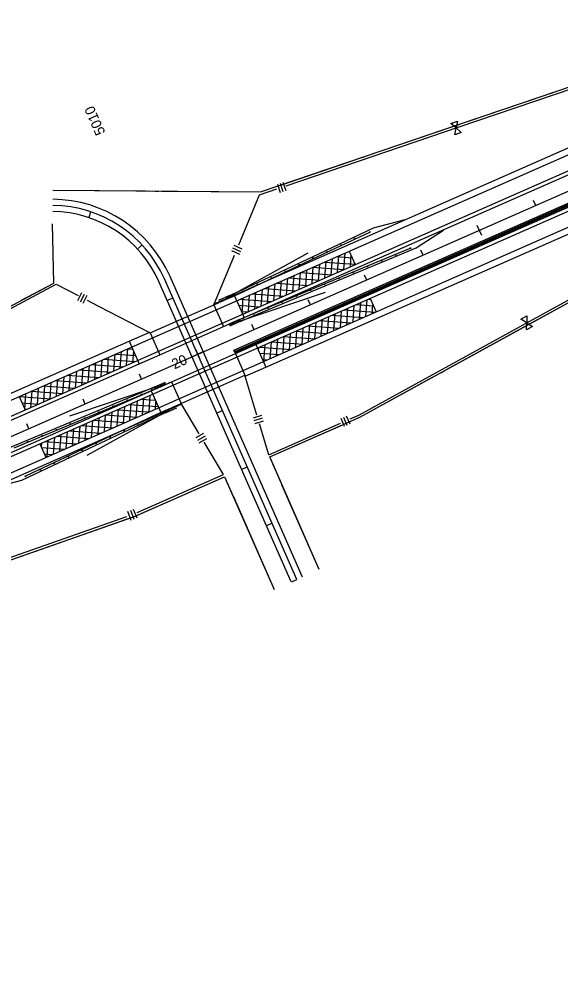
# Model space of a CAD drawing. Extents: x 192699 to 285914, y 194342 to 233219.
# Drawn here: x 245592 to 246471, y 222360 to 223895 of the extents above; entities that cross this region are included whole.
import ezdxf

# ---------------------------------------------------------------- set-up
doc = ezdxf.new("R2010")
doc.units = 0
for name, color, linetype in [('CENT LINE', 7, 'Continuous'), ('CONCRETE', 7, 'Continuous'), ('GUARDRAIL', 7, 'Continuous'), ('PAVEMENT TRANSITION', 7, 'Continuous'), ('R-W - CofA', 7, 'Continuous'), ('R_Draft', 7, 'Continuous'), ('R_Proposed Guardrail', 7, 'Continuous'), ('ROAD', 7, 'Continuous'), ('SHOULDER', 7, 'Continuous'), ('STATIONING1', 7, 'Continuous'), ('STATIONING2', 7, 'Continuous'), ('WRSF', 7, 'Continuous')]:
    doc.layers.add(name, color=color, linetype=linetype)

msp = doc.modelspace()

# ---------------------------------------------------------------- linework, layer by layer
at = {"layer": 'CENT LINE'}
for p, q in [((229622.3, 216190.7), (246993.1, 223840)), ((245646.8, 223592.4), (245646.7, 223592.4)), ((246043.2, 222984.7), (245828.2, 223473))]:
    msp.add_line(p, q, dxfattribs=at)
msp.add_arc((245645.1, 223392.4), 200, 23.7666, 89.5335, dxfattribs=at)
at = {"layer": 'CONCRETE'}
for p, q in [((245941.1, 223357.1), (247000.3, 223823.5)), ((245942.7, 223353.4), (247001.9, 223819.9)), ((245942.7, 223353.4), (245941.1, 223357.1))]:
    msp.add_line(p, q, dxfattribs=at)
at = {"layer": 'GUARDRAIL'}
for p, q in [((245929.5, 223442.3), (246061.8, 223515.5)), ((245946.7, 223403.1), (246090, 223451.3)), ((245817.3, 223298.4), (245674, 223250.2)), ((245834.6, 223259.2), (245702.3, 223186.1))]:
    msp.add_line(p, q, dxfattribs=at)
at = {"layer": 'PAVEMENT TRANSITION'}
for p, q in [((246109.6, 223483.7), (246111.5, 223510.8)), ((246119.9, 223488.3), (246121.9, 223515.4)), ((246127.3, 223517.8), (246128.8, 223517.7)), ((246128.5, 223518.3), (246138.2, 223496.3)), ((246130.3, 223492.9), (246131.6, 223511.2)), ((246078.5, 223470.1), (246080.5, 223497.2)), ((246088.1, 223500.5), (246137.9, 223497)), ((246088.9, 223474.6), (246090.8, 223501.7)), ((246099.2, 223479.2), (246101.2, 223506.3)), ((246107.7, 223509.2), (246133.3, 223507.3)), ((246047.4, 223456.4), (246049.4, 223483.5)), ((246049, 223483.3), (246100.2, 223479.6)), ((246057.8, 223461), (246059.7, 223488)), ((246068.1, 223465.5), (246070.1, 223492.6)), ((246068.6, 223491.9), (246119.7, 223488.2)), ((246006, 223438.2), (246008, 223465.2)), ((246009.9, 223466.1), (246061, 223462.4)), ((246016.4, 223442.7), (246018.3, 223469.8)), ((246026.7, 223447.3), (246028.7, 223474.4)), ((246029.4, 223474.7), (246080.6, 223471)), ((246037.1, 223451.8), (246039, 223478.9)), ((245975, 223424.5), (245976.9, 223451.6)), ((245985.3, 223429), (245987.3, 223456.1)), ((245990.3, 223457.4), (246041.5, 223453.8)), ((245995.7, 223433.6), (245997.6, 223460.7)), ((245945.8, 223436.9), (245945.9, 223437.9)), ((245951.2, 223440.2), (246002.3, 223436.5)), ((245954.4, 223417.4), (245956.2, 223442.4)), ((245964.6, 223419.9), (245966.6, 223447)), ((245970.7, 223448.8), (246021.9, 223445.1)), ((246145.2, 223407.6), (246147.1, 223434.7)), ((246155.5, 223412.2), (246157.5, 223439.3)), ((246158.8, 223439.9), (246163.2, 223439.6)), ((246162.3, 223441.4), (246172, 223419.5)), ((245948.7, 223430.4), (245982.8, 223427.9)), ((245953.2, 223420), (245963.2, 223419.3)), ((246114.1, 223394), (246116, 223421)), ((246119.7, 223422.6), (246170.8, 223419)), ((246124.4, 223398.5), (246126.4, 223425.6)), ((246134.8, 223403.1), (246136.7, 223430.2)), ((246139.2, 223431.3), (246167.7, 223429.2)), ((246165.9, 223416.8), (246166.9, 223431.1)), ((246080.5, 223405.4), (246131.7, 223401.7)), ((246083, 223380.3), (246085, 223407.4)), ((246093.4, 223384.8), (246095.3, 223411.9)), ((246100.1, 223414), (246151.3, 223410.3)), ((246103.7, 223389.4), (246105.7, 223416.5)), ((246041.4, 223388.2), (246092.6, 223384.5)), ((246041.6, 223362), (246043.6, 223389.1)), ((246052, 223366.6), (246053.9, 223393.7)), ((246061, 223396.8), (246112.1, 223393.1)), ((246062.3, 223371.2), (246064.3, 223398.2)), ((246072.7, 223375.7), (246074.6, 223402.8)), ((246010.5, 223348.4), (246012.5, 223375.4)), ((246020.9, 223352.9), (246022.9, 223380)), ((246021.8, 223379.5), (246073, 223375.9)), ((246031.3, 223357.5), (246033.2, 223384.6)), ((245766.6, 223332.7), (245768.6, 223359.8)), ((245768.2, 223359.6), (245776.7, 223359)), ((245981.1, 223356.8), (245981.4, 223361.8)), ((245982.7, 223362.3), (246033.9, 223358.6)), ((245989.8, 223339.2), (245991.8, 223366.3)), ((246000.2, 223343.8), (246002.1, 223370.9)), ((246002.2, 223370.9), (246053.4, 223367.2)), ((245729, 223342.4), (245780.2, 223338.7)), ((245735.6, 223319.1), (245737.5, 223346.1)), ((245745.9, 223323.6), (245747.9, 223350.7)), ((245748.6, 223351), (245781.2, 223348.7)), ((245756.3, 223328.2), (245758.2, 223355.3)), ((245777, 223337.3), (245778.3, 223355.4)), ((245983.1, 223352.3), (246014.3, 223350)), ((245987.6, 223341.9), (245994.7, 223341.4)), ((245694.1, 223300.8), (245696.1, 223327.9)), ((245704.5, 223305.4), (245706.5, 223332.5)), ((245709.5, 223333.8), (245760.6, 223330.1)), ((245714.9, 223309.9), (245716.8, 223337)), ((245725.2, 223314.5), (245727.2, 223341.6)), ((245663.1, 223287.1), (245665, 223314.2)), ((245670.3, 223316.5), (245721.5, 223312.9)), ((245673.4, 223291.7), (245675.4, 223318.8)), ((245683.8, 223296.3), (245685.7, 223323.3)), ((245689.9, 223325.2), (245741.1, 223321.5)), ((245621.7, 223268.9), (245623.6, 223296)), ((245631.2, 223299.3), (245682.4, 223295.6)), ((245632, 223273.5), (245634, 223300.5)), ((245642.4, 223278), (245644.3, 223305.1)), ((245650.8, 223307.9), (245701.9, 223304.2)), ((245652.7, 223282.6), (245654.7, 223309.7)), ((245592, 223282.1), (245601.7, 223260.1)), ((245592, 223282.1), (245643.2, 223278.4)), ((245592.5, 223281.1), (245592.6, 223282.3)), ((245601.1, 223261.5), (245602.9, 223286.9)), ((245611.3, 223264.3), (245613.3, 223291.4)), ((245611.6, 223290.7), (245662.8, 223287)), ((245803.1, 223257), (245805.1, 223284.1)), ((245596.6, 223271.7), (245623.7, 223269.8)), ((245761.7, 223238.8), (245763.7, 223265.9)), ((245771.2, 223269.2), (245817.7, 223265.9)), ((245772.1, 223243.3), (245774, 223270.4)), ((245782.4, 223247.9), (245784.4, 223275)), ((245790.8, 223277.8), (245813.1, 223276.2)), ((245792.8, 223252.5), (245794.7, 223279.5)), ((245813.5, 223261.6), (245814.3, 223273.5)), ((245601.1, 223261.4), (245604.1, 223261.2)), ((245730.7, 223225.1), (245732.6, 223252.2)), ((245732.1, 223252), (245783.3, 223248.3)), ((245741, 223229.7), (245743, 223256.8)), ((245751.4, 223234.2), (245753.3, 223261.3)), ((245751.7, 223260.6), (245802.8, 223256.9)), ((245692.9, 223234.7), (245744.1, 223231)), ((245699.6, 223211.4), (245701.5, 223238.5)), ((245709.9, 223216), (245711.9, 223243.1)), ((245712.5, 223243.3), (245763.7, 223239.7)), ((245720.3, 223220.6), (245722.3, 223247.6)), ((245658.2, 223193.2), (245660.1, 223220.3)), ((245668.5, 223197.8), (245670.5, 223224.8)), ((245673.4, 223226.1), (245724.6, 223222.4)), ((245678.9, 223202.3), (245680.8, 223229.4)), ((245689.2, 223206.9), (245691.2, 223234)), ((245625.9, 223205.2), (245635.5, 223183.2)), ((245628.5, 223199.2), (245629.1, 223206.6)), ((245634.2, 223208.9), (245685.4, 223205.2)), ((245637.5, 223184.1), (245639.4, 223211.2)), ((245647.8, 223188.6), (245649.8, 223215.7)), ((245653.8, 223217.5), (245705, 223213.8)), ((245628.5, 223199.3), (245665.9, 223196.6)), ((245633, 223188.9), (245646.3, 223188))]:
    msp.add_line(p, q, dxfattribs=at)
at = {"layer": 'R-W - CofA'}
for p, q in [((246293.6, 223725.7), (246304.3, 223729.3)), ((246304.3, 223729.3), (246302.1, 223718.3)), ((246302.1, 223718.3), (246293.6, 223725.7)), ((246299.9, 223707.3), (246302.1, 223718.3)), ((246310.5, 223710.9), (246299.9, 223707.3)), ((246302.1, 223718.3), (246310.5, 223710.9)), ((246011.7, 223627.2), (246016.3, 223613.6)), ((246016.2, 223628.7), (246020.8, 223615.2)), ((246020.7, 223630.3), (246025.3, 223616.7)), ((245646.9, 223617.2), (245984.5, 223614.4)), ((245940.8, 223527.7), (245953.9, 223521.9)), ((245937, 223519), (245950.1, 223513.2)), ((245938.9, 223523.3), (245952, 223517.6)), ((245687.4, 223437.9), (245693.9, 223450.7)), ((245691.7, 223435.8), (245698.1, 223448.5)), ((245696, 223433.6), (245702.4, 223446.4)), ((246407.3, 223407.4), (246417.1, 223412.8)), ((246416.9, 223401.6), (246407.3, 223407.4)), ((246417.1, 223412.8), (246416.9, 223401.6)), ((246416.6, 223390.4), (246416.9, 223401.6)), ((246426.5, 223395.8), (246416.6, 223390.4)), ((246416.9, 223401.6), (246426.5, 223395.8)), ((245972.7, 223247.5), (245986.4, 223251.7)), ((246123.4, 223250.5), (246129.2, 223237.4)), ((245974, 223243), (245987.7, 223247.1)), ((245975.4, 223238.4), (245989.1, 223242.5)), ((246114.7, 223246.7), (246120.5, 223233.6)), ((246119.1, 223248.6), (246124.8, 223235.5)), ((245880, 223215.2), (245892.4, 223222.3)), ((245882.4, 223211), (245894.8, 223218.2)), ((245884.7, 223206.9), (245897.1, 223214)), ((246079.8, 223000.8), (245999.2, 223183.8)), ((245926, 223151.6), (246006.6, 222968.6)), ((245773.2, 223097.2), (245778.2, 223082.9)), ((245777.1, 223098.7), (245783.2, 223084.8)), ((245768.4, 223095.5), (245773.4, 223081.2))]:
    msp.add_line(p, q, dxfattribs=at)
for points in [[(245984.5, 223614.4), (246744.8, 223872.8), (246940.7, 223959)], [(246307.4, 223720.1), (246617.2, 223825.4)], [(246306.2, 223723.7), (246448.7, 223772.1)], [(246453.3, 223773.7), (246458.8, 223775.6)], [(246463.4, 223777.1), (246468.9, 223779)], [(245999.2, 223183.8), (246145.7, 223248.3), (246849.6, 223634.8), (247045.5, 223721)], [(246025.8, 223624.4), (246307.4, 223720.1)], [(246158.3, 223673.5), (246306.2, 223723.7)], [(246025, 223628.2), (246133.5, 223665.1)], [(246138.1, 223666.6), (246143.6, 223668.5)], [(246148.2, 223670), (246153.7, 223671.9)], [(245982.5, 223609.7), (246011, 223619.4)], [(245984.5, 223614.4), (246009.8, 223623)], [(245646.9, 223617.2), (245797.5, 223615.9)], [(245802.3, 223615.9), (245808.2, 223615.8)], [(245813, 223615.8), (245818.8, 223615.8)], [(245823.6, 223615.7), (245984.5, 223614.4)], [(245948.9, 223528.4), (245982.5, 223609.7)], [(245594.9, 223437.9), (245648.4, 223466.4), (245646.5, 223562.4)], [(245648.4, 223466.4), (245646.5, 223562.4)], [(246421.8, 223404.3), (246708.6, 223561.7)], [(245908.6, 223430.8), (245942.1, 223511.8)], [(240059.9, 220939.9), (241158.1, 221423.5), (241253.7, 221454.7), (244822.9, 223026.4), (245648.4, 223466.4)], [(246423.6, 223400.9), (246555.6, 223473.4)], [(245440.2, 223351.1), (245652.5, 223464.3)], [(245652.5, 223464.3), (245687.8, 223446)], [(245702.4, 223438.4), (245721.3, 223428.6)], [(245721.3, 223428.6), (245805, 223385.2)], [(246129.8, 223245.5), (246144, 223251.8), (246421.8, 223404.3)], [(246286.8, 223325.8), (246423.6, 223400.9)], [(245978.6, 223251.9), (245959, 223316.4)], [(246131.3, 223242), (246145.7, 223248.3), (246263.9, 223313.2)], [(246268.1, 223315.6), (246273.2, 223318.4)], [(246277.4, 223320.7), (246282.5, 223323.5)], [(245884.8, 223221.1), (245855.4, 223270.8)], [(245998.1, 223187.5), (245982.9, 223237.7)], [(245998.1, 223187.5), (246114.1, 223238.6)], [(246008.6, 223162.5), (245999.2, 223183.8), (246115.6, 223235.1)], [(245923.9, 223155.1), (245892.8, 223207.7)], [(246012.9, 223152.7), (246010.6, 223158.1)], [(239985.6, 220612.2), (240172.7, 220683.7), (241545.5, 221288.2), (241633, 221337.6), (244927.7, 222788.5), (245779.6, 223087.1), (245926, 223151.6)], [(245783.8, 223093.4), (245923.9, 223155.1)], [(245785.5, 223089.7), (245926, 223151.6), (245928.6, 223145.8)], [(246017.2, 223143), (246014.9, 223148.3)], [(245930.6, 223141.1), (245933.1, 223135.4)], [(245935.2, 223130.7), (245937.7, 223125.1)], [(246079.8, 223000.8), (246019.2, 223138.6)], [(245939.8, 223120.4), (246006.6, 222968.6)], [(245439.1, 222972), (245767.1, 223087)], [(245617.5, 223030.3), (245768.4, 223083.2)], [(245596.2, 223022.8), (245602, 223024.9)], [(245606.9, 223026.6), (245612.7, 223028.6)]]:
    msp.add_lwpolyline(points, dxfattribs=at)
at = {"layer": 'R_Draft'}
for p, q in [((246168.2, 223555.9), (246219.4, 223569.3)), ((246068.7, 223508.9), (246168.2, 223555.9)), ((246115.4, 223527.1), (246160.7, 223548.4)), ((246161.8, 223550.1), (246160.7, 223548.4)), ((246162.7, 223548.3), (246160.7, 223548.4)), ((246162.7, 223548.3), (246161.8, 223550.1)), ((245957.2, 223452.4), (246115.4, 223527.1)), ((245955.7, 223455.6), (246068.7, 223508.9)), ((245932.9, 223445.4), (245955.7, 223455.6)), ((245934.3, 223442.2), (245957.2, 223452.4)), ((245932.9, 223445.4), (245915.8, 223437.8)), ((245934.3, 223442.2), (245917.2, 223434.6)), ((245829.7, 223259.3), (245846.8, 223267)), ((245829.7, 223259.3), (245806.9, 223249.1)), ((245831.1, 223256.1), (245808.3, 223245.9)), ((245831.1, 223256.1), (245848.2, 223263.8)), ((245806.9, 223249.1), (245648.6, 223174.4)), ((245808.4, 223245.9), (245695.3, 223192.5)), ((245695.3, 223192.5), (245595.8, 223145.6)), ((245648.6, 223174.4), (245603.4, 223153)), ((245595.8, 223145.6), (245544.6, 223132.2)), ((245601.4, 223153.2), (245603.4, 223153)), ((245601.4, 223153.2), (245602.3, 223151.4)), ((245602.3, 223151.4), (245603.4, 223153))]:
    msp.add_line(p, q, dxfattribs=at)
for centre in [(246115.2, 223527.8), (246137.8, 223538.5), (246092.5, 223517.1), (246047.3, 223495.8), (246069.9, 223506.5), (246024.7, 223485.1), (246002.1, 223474.5), (245956.9, 223453.1), (245979.5, 223463.8), (245918.3, 223435.9), (245919.8, 223436.5), (245921.2, 223437.2), (245922.6, 223437.8), (245924, 223438.4), (245925.5, 223439.1), (245928.3, 223440.4), (245931.2, 223441.6), (245934, 223442.9), (245939.7, 223445.5), (245842.8, 223264.4), (245844.3, 223265), (245845.7, 223265.6), (245824.3, 223256.1), (245830, 223258.6), (245832.9, 223259.9), (245835.7, 223261.2), (245838.6, 223262.5), (245840, 223263.1), (245841.4, 223263.7), (245784.6, 223237.7), (245807.2, 223248.4), (245762, 223227), (245716.7, 223205.7), (245739.3, 223216.4), (245694.1, 223195), (245648.9, 223173.7), (245671.5, 223184.4), (245626.3, 223163)]:
    msp.add_circle(centre, 0.75, dxfattribs=at)
at = {"layer": 'R_Proposed Guardrail'}
for p, q in [((246237.2, 223523.4), (246281.5, 223552.4)), ((246089.5, 223461.8), (246237.2, 223523.4)), ((246180.5, 223503.5), (246226.7, 223522.7)), ((246227.9, 223524.3), (246226.7, 223522.7)), ((246228.6, 223522.5), (246226.7, 223522.7)), ((246227.9, 223524.3), (246228.6, 223522.5)), ((245972.8, 223417), (246180.5, 223503.5)), ((245974.1, 223413.7), (246089.5, 223461.8)), ((245949.9, 223406.9), (245932.7, 223399.3)), ((245951.3, 223403.7), (245934.1, 223396.1)), ((245949.9, 223406.9), (245972.8, 223417)), ((245951.3, 223403.7), (245974.2, 223413.8)), ((245812.7, 223297.9), (245789.8, 223287.8)), ((245812.7, 223297.9), (245829.9, 223305.4)), ((245814.1, 223294.6), (245831.3, 223302.2)), ((245791.3, 223284.6), (245583.5, 223198)), ((245789.9, 223287.8), (245674.5, 223239.7)), ((245814.1, 223294.6), (245791.3, 223284.6)), ((245674.5, 223239.7), (245526.8, 223178.2))]:
    msp.add_line(p, q, dxfattribs=at)
for centre in [(246203.9, 223512.4), (246180.8, 223502.8), (246134.7, 223483.6), (246157.7, 223493.2), (246088.5, 223464.4), (246111.6, 223474), (246065.4, 223454.7), (246019.2, 223435.5), (246042.3, 223445.1), (245996.2, 223425.9), (245944.5, 223403.7), (245947.3, 223404.9), (245950.2, 223406.2), (245955.9, 223408.7), (245973.1, 223416.3), (245934.5, 223399.3), (245935.9, 223399.9), (245937.3, 223400.5), (245938.8, 223401.2), (245940.2, 223401.8), (245941.6, 223402.4), (245813.8, 223295.3), (245816.7, 223296.6), (245819.6, 223297.9), (245822.4, 223299.1), (245823.8, 223299.7), (245825.3, 223300.4), (245826.7, 223301), (245828.1, 223301.6), (245829.6, 223302.3), (245790.9, 223285.3), (245808.1, 223292.8), (245744.8, 223266), (245767.9, 223275.6), (245721.7, 223256.4), (245675.5, 223237.2), (245698.6, 223246.8), (245652.5, 223227.6), (245606.3, 223208.3), (245629.4, 223217.9)]:
    msp.add_circle(centre, 0.75, dxfattribs=at)
at = {"layer": 'ROAD'}
for p, q in [((239472.3, 220587.2), (246971.3, 223889.4)), ((229610.2, 216218.1), (246981, 223867.5)), ((229634.4, 216163.2), (247005.2, 223812.6)), ((239989.5, 220696.9), (247014.8, 223790.6)), ((246034.1, 222980.7), (245819, 223469)), ((246052.4, 222988.7), (245837.3, 223477.1)), ((245805, 223385.2), (245917.2, 223434.6)), ((245908, 223432.1), (245941.4, 223446.9)), ((245941.4, 223446.9), (245957.5, 223410.2)), ((245924.1, 223395.5), (245957.5, 223410.2)), ((245820.6, 223349.9), (245932.7, 223399.3)), ((245771, 223371.8), (245804.4, 223386.5)), ((245771, 223371.8), (245787.1, 223335.2)), ((245943.5, 223351.6), (245976.9, 223366.3)), ((245976.9, 223366.3), (245993, 223329.7)), ((245787.1, 223335.2), (245820.6, 223349.9)), ((245831.3, 223302.2), (245943.5, 223351.6)), ((245959.6, 223315), (245993, 223329.7)), ((245846.8, 223267), (245959, 223316.4)), ((245806.5, 223291.3), (245839.9, 223306)), ((245806.5, 223291.3), (245822.6, 223254.7)), ((245822.6, 223254.7), (245856, 223269.4))]:
    msp.add_line(p, q, dxfattribs=at)
for points in [[(245908.6, 223430.8), (245924.1, 223395.5)], [(245805, 223385.2), (245820.6, 223349.9)], [(245943.5, 223351.6), (245959, 223316.4)], [(245839.9, 223306), (245855.4, 223270.8)]]:
    msp.add_lwpolyline(points, dxfattribs=at)
for radius in [210, 190]:
    msp.add_arc((245645.1, 223392.4), radius, 23.7666, 89.5335, dxfattribs=at)
at = {"layer": 'SHOULDER'}
for p, q in [((245941.4, 223446.9), (246967.3, 223898.6)), ((245957.5, 223410.2), (246983.4, 223862)), ((245976.9, 223366.3), (247002.7, 223818.1)), ((245993, 223329.7), (247018.9, 223781.4)), ((245078.8, 223067), (245771, 223371.8)), ((245094.9, 223030.4), (245787.1, 223335.2)), ((245114.2, 222986.4), (245806.5, 223291.3)), ((245130.4, 222949.8), (245822.6, 223254.7))]:
    msp.add_line(p, q, dxfattribs=at)
at = {"layer": 'STATIONING1'}
for points in [[(246427.5, 223600.8), (246431.1, 223592.6)], [(246336, 223560.5), (246343.2, 223544)], [(246244.5, 223520.2), (246248.1, 223512)], [(246152.9, 223479.9), (246156.6, 223471.7)], [(246061.4, 223439.6), (246065.1, 223431.4)], [(245969.9, 223399.3), (245973.5, 223391.1)], [(245878.4, 223359), (245885.6, 223342.5)], [(245786.9, 223318.7), (245790.5, 223310.5)], [(245695.4, 223278.4), (245699, 223270.2)], [(245603.8, 223238.1), (245607.5, 223229.9)]]:
    msp.add_lwpolyline(points, dxfattribs=at)
at = {"layer": 'STATIONING2'}
for points in [[(245705.9, 223573.5), (245708.8, 223582)], [(245785.3, 223522.2), (245791.9, 223528.3)], [(245833.5, 223438.7), (245841.7, 223442.3)], [(245873.8, 223347.1), (245890.3, 223354.4)], [(245914.1, 223255.6), (245922.3, 223259.2)], [(245954.4, 223164.1), (245962.6, 223167.7)], [(245994.7, 223072.6), (246002.9, 223076.2)], [(246035, 222981.1), (246043.2, 222984.7)]]:
    msp.add_lwpolyline(points, dxfattribs=at)
at = {"layer": 'WRSF'}
msp.add_line((245941.9, 223355.3), (247001.1, 223821.7), dxfattribs=at)

# ---------------------------------------------------------------- texts
at = {"layer": 'STATIONING1'}
msp.add_text('5010', height=16.5, rotation=113.7667, dxfattribs=at).set_placement((245732.5, 223710.8))
at = {"layer": 'STATIONING2'}
msp.add_text('20', height=16.5, rotation=23.7666, dxfattribs=at).set_placement((245844.4, 223326))

doc.saveas('drawing.dxf')
